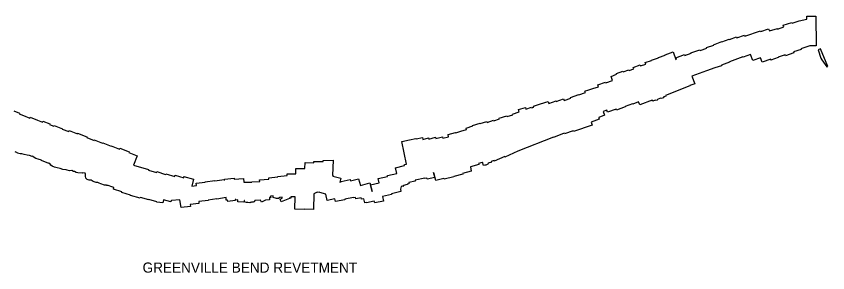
# Model space of a CAD drawing. Extents: x 2650582 to 3923188, y 277893 to 989177.
# Drawn here: x 3663705 to 3676472, y 511818 to 515862 of the extents above; entities that cross this region are included whole.
import ezdxf

# ---------------------------------------------------------------- set-up
doc = ezdxf.new("R2010")
doc.units = 0
doc.layers.add('Level 3', color=7, linetype='Continuous')

msp = doc.modelspace()

# ---------------------------------------------------------------- linework, layer by layer
at = {"layer": 'Level 3'}
msp.add_line((3669844, 513531), (3669769, 513886), dxfattribs=at)
for points in [[(3674083, 515208), (3674218, 515256), (3674223, 515244), (3674321, 515279), (3674319, 515284), (3674459, 515332), (3674463, 515322), (3674568, 515358), (3674565, 515366), (3674679, 515403), (3674676, 515411), (3674807, 515461), (3674808, 515457), (3674922, 515501), (3674924, 515496), (3675034, 515536), (3675040, 515522), (3675163, 515564), (3675170, 515545), (3675416, 515632), (3675420, 515621), (3675541, 515663), (3675554, 515629), (3675679, 515669), (3675682, 515660), (3675781, 515694), (3675773, 515720), (3675909, 515762), (3675912, 515754), (3676023, 515791), (3676143, 515817), (3676145, 515862), (3676284, 515860), (3676289, 515394)], [(3676289, 515394), (3676189, 515393), (3676051, 515345), (3676053, 515339), (3675933, 515298), (3675936, 515286), (3675807, 515239), (3675802, 515252), (3675692, 515216), (3675694, 515211), (3675578, 515171), (3675574, 515182), (3675439, 515136), (3675412, 515206), (3675292, 515164), (3675258, 515257), (3675140, 515214), (3675135, 515224), (3674925, 515144), (3674928, 515138), (3674799, 515090), (3674803, 515080), (3674697, 515046), (3674562, 515000), (3674336, 514918), (3674379, 514797), (3674300, 514770)], [(3676319, 515330), (3676362, 515202), (3676378, 515174), (3676459, 515065), (3676472, 515070), (3676358, 515345)], [(3676358, 515345), (3676319, 515330)], [(3671848, 514426), (3671842, 514444), (3671952, 514481), (3671952, 514480), (3672071, 514520), (3672082, 514486), (3672199, 514526), (3672201, 514519), (3672317, 514559), (3672326, 514534), (3672429, 514570), (3672425, 514581), (3672558, 514626), (3672558, 514625), (3672659, 514660), (3672652, 514680), (3672655, 514681), (3672653, 514685), (3672698, 514696), (3672777, 514723), (3672777, 514722), (3672863, 514751), (3672853, 514779), (3672977, 514824), (3672982, 514811), (3673085, 514849), (3673062, 514913), (3673151, 514946), (3673147, 514957), (3673248, 514994), (3673252, 514985), (3673342, 515018), (3673346, 515007), (3673420, 515034), (3673413, 515053), (3673522, 515093), (3673528, 515077), (3673611, 515107), (3673602, 515130), (3673701, 515166), (3673701, 515167), (3673810, 515207), (3673809, 515209), (3673916, 515248), (3673915, 515253), (3674039, 515298), (3674082, 515180), (3674092, 515184), (3674083, 515208)], [(3674300, 514770), (3674303, 514763), (3673919, 514613), (3673923, 514604), (3673892, 514591), (3673881, 514574), (3673856, 514565), (3673839, 514570), (3673793, 514551), (3673787, 514539), (3673770, 514533), (3673756, 514538), (3673718, 514521), (3673711, 514536), (3673518, 514464), (3673497, 514514), (3673403, 514476), (3673401, 514480), (3673283, 514436), (3673285, 514433), (3673148, 514381), (3673141, 514398), (3673008, 514350), (3672995, 514381), (3672941, 514362), (3672960, 514304), (3672869, 514267), (3672869, 514264), (3672871, 514258), (3672870, 514258), (3672870, 514257), (3672877, 514238), (3672751, 514191), (3672765, 514145), (3672473, 514043), (3672468, 514054), (3672330, 514007), (3672326, 514017)], [(3669769, 513886), (3669890, 513912), (3669890, 513911), (3669994, 513934), (3669996, 513927), (3670096, 513950), (3670103, 513919), (3670193, 513943), (3670197, 513926), (3670300, 513953), (3670305, 513932), (3670411, 513960), (3670417, 513937), (3670508, 513961), (3670498, 513997), (3670618, 514029), (3670620, 514022), (3670700, 514048), (3670700, 514048), (3670790, 514077), (3670782, 514099), (3670886, 514132), (3670884, 514138), (3671002, 514177), (3671004, 514171), (3671108, 514204), (3671112, 514189), (3671216, 514223), (3671219, 514214), (3671309, 514243), (3671304, 514256), (3671422, 514294), (3671427, 514279), (3671516, 514309), (3671513, 514318), (3671617, 514352), (3671605, 514389), (3671715, 514425), (3671724, 514399), (3671812, 514428), (3671816, 514416), (3671848, 514426)], [(3663665, 514372), (3663754, 514332), (3663750, 514325), (3663817, 514297), (3663818, 514298), (3663919, 514257), (3663925, 514272), (3664040, 514225), (3664039, 514223), (3664118, 514191), (3664125, 514207), (3664232, 514163)], [(3664232, 514163), (3664229, 514154), (3664295, 514127), (3664300, 514139), (3664430, 514088), (3664428, 514082), (3664530, 514043), (3664536, 514059), (3664668, 514008), (3664671, 514016), (3664817, 513959), (3664814, 513950), (3664931, 513905), (3664933, 513911), (3665064, 513860), (3665066, 513865), (3665198, 513813), (3665199, 513817), (3665330, 513765), (3665336, 513780), (3665481, 513723), (3665478, 513715), (3665609, 513663), (3665552, 513515), (3665788, 513447), (3665785, 513436), (3665913, 513396), (3665919, 513413), (3666054, 513368), (3666059, 513378), (3666198, 513333), (3666206, 513356), (3666339, 513313), (3666344, 513335), (3666495, 513295), (3666467, 513185)], [(3672326, 514017), (3672159, 513948), (3672157, 513953), (3671595, 513734), (3671394, 513641), (3671390, 513650), (3671225, 513578), (3671222, 513586), (3671176, 513574), (3671178, 513567), (3671176, 513557), (3671144, 513550), (3671129, 513538), (3671123, 513532), (3671094, 513515), (3671076, 513515), (3671056, 513510), (3671039, 513559), (3671034, 513557), (3671034, 513558), (3670979, 513542), (3670983, 513524), (3670850, 513486), (3670864, 513421), (3670726, 513385), (3670729, 513374), (3670587, 513334), (3670588, 513331), (3670437, 513293), (3670434, 513303), (3670306, 513274), (3670272, 513401), (3670272, 513400), (3670293, 513321), (3670169, 513292)], [(3665240, 513161), (3665208, 513174), (3665151, 513191), (3665132, 513191), (3665124, 513201), (3665094, 513200), (3665037, 513219), (3665009, 513228), (3664986, 513242), (3664961, 513243), (3664917, 513259), (3664883, 513276), (3664854, 513275), (3664820, 513289), (3664801, 513311), (3664797, 513342), (3664794, 513374), (3664788, 513386), (3664746, 513394), (3664743, 513389), (3664676, 513395), (3664648, 513397), (3664622, 513412), (3664606, 513415), (3664582, 513429), (3664542, 513426), (3664504, 513435), (3664488, 513442), (3664437, 513448), (3664394, 513459), (3664351, 513473), (3664308, 513485), (3664271, 513498), (3664248, 513514), (3664231, 513540), (3664219, 513547), (3664216, 513541), (3664101, 513588), (3664104, 513594), (3664052, 513608), (3664015, 513618), (3663957, 513657), (3663954, 513652), (3663914, 513664), (3663876, 513669), (3663829, 513683), (3663791, 513693), (3663764, 513692), (3663727, 513705), (3663723, 513710), (3663687, 513723)], [(3667966, 513351), (3667966, 513377), (3668101, 513379), (3668103, 513464), (3668244, 513461), (3668248, 513554), (3668388, 513551), (3668389, 513572), (3668533, 513571), (3668533, 513590), (3668689, 513595), (3668682, 513350), (3668689, 513349), (3668687, 513339), (3668811, 513309), (3668797, 513246), (3668816, 513251), (3668815, 513255), (3668956, 513289), (3668961, 513269), (3669089, 513301), (3669120, 513194), (3669266, 513233), (3669304, 513097), (3669280, 513203), (3669416, 513237), (3669400, 513306), (3669546, 513338), (3669544, 513350), (3669692, 513381), (3669672, 513472), (3669815, 513508), (3669812, 513523), (3669844, 513531)], [(3666467, 513185), (3666539, 513196), (3666537, 513228), (3666677, 513244), (3666677, 513253), (3666831, 513271), (3666831, 513268), (3666974, 513288), (3666975, 513284), (3666984, 513285), (3666983, 513294), (3667133, 513309), (3667135, 513295), (3667281, 513302), (3667285, 513247), (3667411, 513248), (3667411, 513251), (3667535, 513255), (3667534, 513282), (3667678, 513295), (3667677, 513317), (3667822, 513330), (3667821, 513334), (3667966, 513351)], [(3670169, 513292), (3670164, 513310), (3670135, 513303), (3670133, 513308), (3669983, 513277), (3669980, 513262), (3669880, 513241), (3669883, 513221), (3669855, 513214), (3669856, 513208), (3669797, 513194), (3669789, 513179), (3669779, 513182), (3669762, 513180), (3669749, 513137), (3669757, 513100), (3669609, 513064), (3669611, 513054), (3669469, 513022), (3669484, 512949), (3669346, 512921), (3669338, 512948), (3669215, 512921), (3669213, 512927), (3669187, 512922), (3669172, 512981), (3669139, 512976), (3669133, 512998), (3669049, 512983), (3669042, 513006), (3669013, 513001), (3669012, 513004), (3668875, 512976), (3668877, 512968), (3668729, 512940), (3668719, 512981), (3668599, 512956), (3668577, 513059), (3668481, 513084), (3668476, 513088), (3668440, 513085), (3668440, 513087), (3668439, 513087), (3668389, 513064)], [(3668389, 513064), (3668383, 512817), (3668242, 512819), (3668242, 512815), (3668088, 512819), (3668093, 513014), (3668026, 513013), (3668026, 512996), (3668000, 512994), (3668002, 512988), (3667874, 512935), (3667855, 512979), (3667887, 512995), (3667887, 513010), (3667851, 513005), (3667831, 512987), (3667797, 512988), (3667749, 513003), (3667749, 513029), (3667707, 513026), (3667708, 513006), (3667688, 513004), (3667691, 512967), (3667626, 512960), (3667562, 512931), (3667549, 512963), (3667460, 512959), (3667460, 512946), (3667448, 512946), (3667450, 512938), (3667430, 512929), (3667405, 512930), (3667398, 512925), (3667386, 512927), (3667382, 512923), (3667346, 512924), (3667321, 512924), (3667301, 512933), (3667295, 512956), (3667289, 512956), (3667286, 512929), (3667189, 512936), (3667191, 512967), (3667158, 512963), (3667157, 512973), (3667148, 512973), (3667150, 512956), (3667032, 512942), (3667028, 512964), (3667009, 512963), (3667006, 512996), (3667005, 513002), (3666863, 512980), (3666862, 512984), (3666722, 512964), (3666722, 512956), (3666575, 512941), (3666578, 512908), (3666440, 512892), (3666444, 512860), (3666299, 512849), (3666281, 512970), (3666145, 512955), (3666143, 512961), (3666138, 512937), (3666020, 512966), (3666012, 512918), (3665915, 512933), (3665916, 512935), (3665792, 512975), (3665789, 512967), (3665659, 513006), (3665653, 512993), (3665503, 513037), (3665504, 513043), (3665366, 513085), (3665367, 513093), (3665234, 513137), (3665240, 513161)]]:
    msp.add_lwpolyline(points, dxfattribs=at)

# ---------------------------------------------------------------- texts
msp.add_text('GREENVILLE BEND REVETMENT', height=160, dxfattribs=at).set_placement((3665692, 511820))

doc.saveas('drawing.dxf')
